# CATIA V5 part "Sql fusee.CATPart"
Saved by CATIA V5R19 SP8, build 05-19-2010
Part number: Sql fusee
Publications: "Droite.1", "Droite.2", "Plan.1", "Plan.3", "Plan.5", "Droite.3", "Droite.4"
Bounding box of the stored display mesh (mm): x 400 to 500, y 100 to 140, z -310 to 0
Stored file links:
  C:\Users\ThinkMotion\Desktop\EU_thinkMotion\iao\IAO_MMS_Groupe3\rdalborgo\rdalborgo\Sql fusee.CATPart
  C:\Users\ThinkMotion\Desktop\EU_thinkMotion\iao\IAO_MMS_Groupe3\rdalborgo\rdalborgo\Sql train.CATProduct
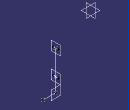
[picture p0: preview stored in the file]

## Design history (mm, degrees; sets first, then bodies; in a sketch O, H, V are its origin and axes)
Set1
  Point1 "B fusee": linked copy from another document
  Point2 "Inf fusee": linked copy from another document
  Point3 "Centre roue": linked copy from another document
  Plane1: linked copy from another document
  Plane2: linked copy from another document
  Point4 "C fusee": linked copy from another document
Set2
  Line1: type PtPt, FirstPoint Point1, SecondPoint Point2
  Line2: type PtPt, FirstPoint Point2, SecondPoint Point3
  Plane3: type OffsetPt, RefPlane Plane1, RefPoint Point2
  Plane4: type OffsetPt, RefPlane Plane2, RefPoint Point4
  Plane5: type OffsetPt, RefPlane Plane2, RefPoint Point1
  Line3: type Normal, RefPoint Point4, RefSkin Plane1, Start -20, End 20
  Line4: type Normal, RefPoint Point1, RefSkin Plane1, Start -20, End 20
Body1 (main body)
